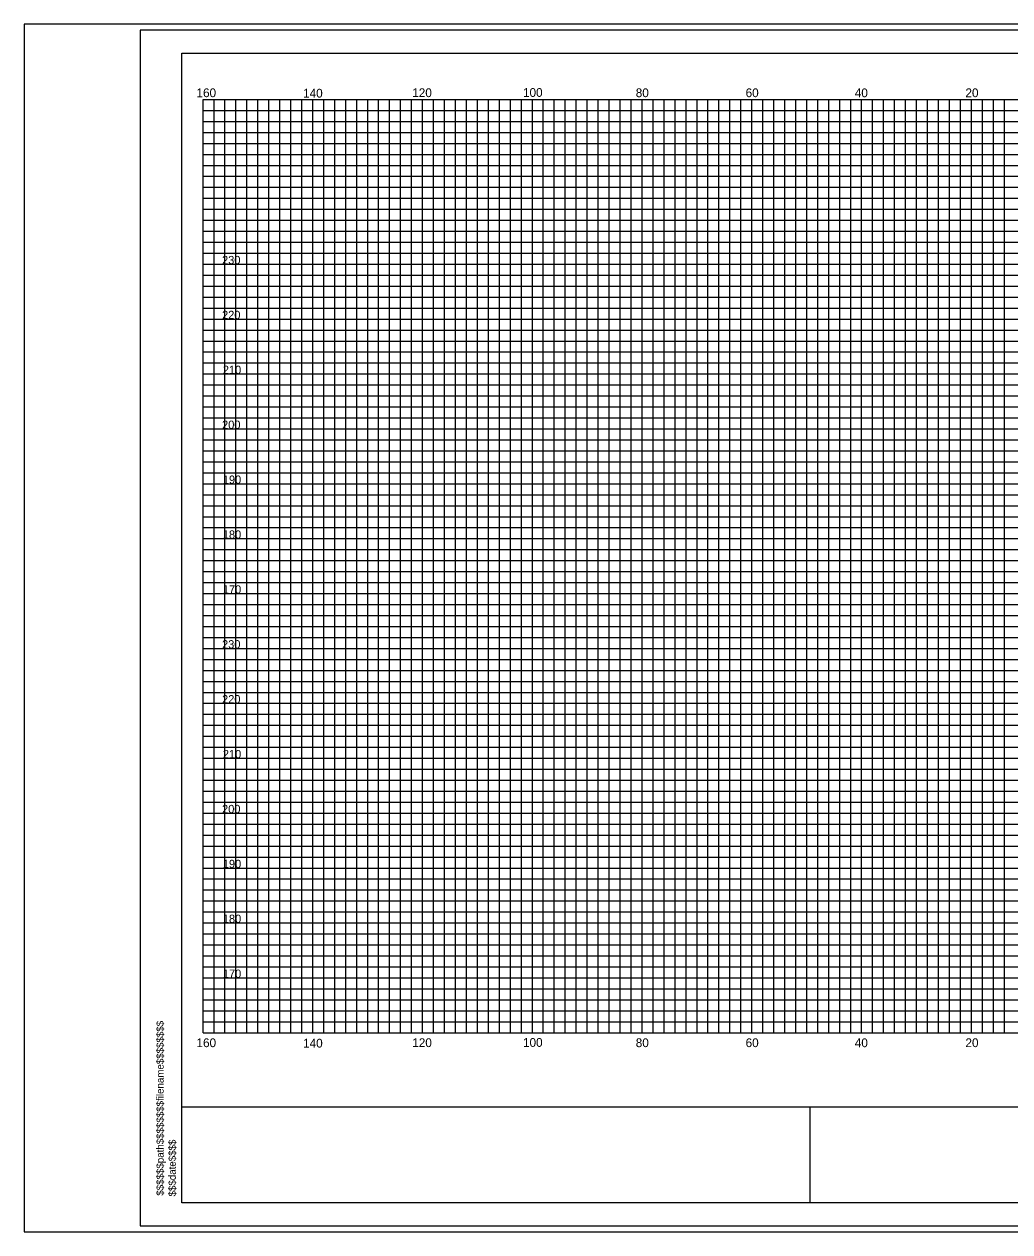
# Model space of a CAD drawing. Extents: x 967 to 1326, y 964 to 3144.
# Drawn here: x 967.4 to 1147, y 963.7 to 1183.7 of the extents above; entities that cross this region are included whole.
import ezdxf

# ---------------------------------------------------------------- set-up
doc = ezdxf.new("R2010")
doc.units = 0
for name, color, linetype in [('Default', 7, 'Continuous'), ('RD_GPK_XS_Cell', 7, 'Continuous'), ('RD_XS_ExGround', 7, 'Continuous'), ('RD_XS_ExPaveRet', 7, 'Continuous'), ('RD_XS_Misc_Line', 7, 'Continuous'), ('RD_XS_TX_Elev_EX', 7, 'Continuous'), ('RD_XS_TX_Station', 7, 'Continuous')]:
    doc.layers.add(name, color=color, linetype=linetype)

msp = doc.modelspace()

# ---------------------------------------------------------------- linework, layer by layer
at = {"layer": 'RD_GPK_XS_Cell'}
for p, q in [((1000, 1170), (1320, 1170)), ((1000, 1000), (1000, 1170)), ((1010, 1000), (1010, 1170)), ((1020, 1000), (1020, 1170)), ((1030, 1000), (1030, 1170)), ((1040, 1000), (1040, 1170)), ((1050, 1000), (1050, 1170)), ((1060, 1000), (1060, 1170)), ((1070, 1000), (1070, 1170)), ((1080, 1000), (1080, 1170)), ((1090, 1000), (1090, 1170)), ((1100, 1000), (1100, 1170)), ((1110, 1000), (1110, 1170)), ((1120, 1000), (1120, 1170)), ((1130, 1000), (1130, 1170)), ((1140, 1000), (1140, 1170)), ((1000, 1160), (1320, 1160)), ((1000, 1150), (1320, 1150)), ((1000, 1140), (1320, 1140)), ((1000, 1130), (1320, 1130)), ((1000, 1120), (1320, 1120)), ((1000, 1110), (1320, 1110)), ((1000, 1100), (1320, 1100)), ((1000, 1090), (1320, 1090)), ((1000, 1080), (1320, 1080)), ((1000, 1070), (1320, 1070)), ((1000, 1060), (1320, 1060)), ((1000, 1050), (1320, 1050)), ((1000, 1040), (1320, 1040)), ((1000, 1030), (1320, 1030)), ((1000, 1020), (1320, 1020)), ((1000, 1010), (1320, 1010)), ((1000, 1000), (1320, 1000))]:
    msp.add_line(p, q, dxfattribs=at)
at = {"layer": 'RD_XS_ExGround'}
for p, q in [((1002, 1000), (1002, 1170)), ((1004, 1000), (1004, 1170)), ((1006, 1000), (1006, 1170)), ((1008, 1000), (1008, 1170)), ((1012, 1000), (1012, 1170)), ((1014, 1000), (1014, 1170)), ((1016, 1000), (1016, 1170)), ((1018, 1000), (1018, 1170)), ((1022, 1000), (1022, 1170)), ((1024, 1000), (1024, 1170)), ((1026, 1000), (1026, 1170)), ((1028, 1000), (1028, 1170)), ((1032, 1000), (1032, 1170)), ((1034, 1000), (1034, 1170)), ((1036, 1000), (1036, 1170)), ((1038, 1000), (1038, 1170)), ((1042, 1000), (1042, 1170)), ((1044, 1000), (1044, 1170)), ((1046, 1000), (1046, 1170)), ((1048, 1000), (1048, 1170)), ((1052, 1000), (1052, 1170)), ((1054, 1000), (1054, 1170)), ((1056, 1000), (1056, 1170)), ((1058, 1000), (1058, 1170)), ((1062, 1000), (1062, 1170)), ((1064, 1000), (1064, 1170)), ((1066, 1000), (1066, 1170)), ((1068, 1000), (1068, 1170)), ((1072, 1000), (1072, 1170)), ((1074, 1000), (1074, 1170)), ((1076, 1000), (1076, 1170)), ((1078, 1000), (1078, 1170)), ((1082, 1000), (1082, 1170)), ((1084, 1000), (1084, 1170)), ((1086, 1000), (1086, 1170)), ((1088, 1000), (1088, 1170)), ((1092, 1000), (1092, 1170)), ((1094, 1000), (1094, 1170)), ((1096, 1000), (1096, 1170)), ((1098, 1000), (1098, 1170)), ((1102, 1000), (1102, 1170)), ((1104, 1000), (1104, 1170)), ((1106, 1000), (1106, 1170)), ((1108, 1000), (1108, 1170)), ((1112, 1000), (1112, 1170)), ((1114, 1000), (1114, 1170)), ((1116, 1000), (1116, 1170)), ((1118, 1000), (1118, 1170)), ((1122, 1000), (1122, 1170)), ((1124, 1000), (1124, 1170)), ((1126, 1000), (1126, 1170)), ((1128, 1000), (1128, 1170)), ((1132, 1000), (1132, 1170)), ((1134, 1000), (1134, 1170)), ((1136, 1000), (1136, 1170)), ((1138, 1000), (1138, 1170)), ((1142, 1000), (1142, 1170)), ((1144, 1000), (1144, 1170)), ((1146, 1000), (1146, 1170)), ((1000, 1168), (1320, 1168)), ((1000, 1166), (1320, 1166)), ((1000, 1164), (1320, 1164)), ((1000, 1162), (1320, 1162)), ((1000, 1158), (1320, 1158)), ((1000, 1156), (1320, 1156)), ((1000, 1154), (1320, 1154)), ((1000, 1152), (1320, 1152)), ((1000, 1148), (1320, 1148)), ((1000, 1146), (1320, 1146)), ((1000, 1144), (1320, 1144)), ((1000, 1142), (1320, 1142)), ((1000, 1138), (1320, 1138)), ((1000, 1136), (1320, 1136)), ((1000, 1134), (1320, 1134)), ((1000, 1132), (1320, 1132)), ((1000, 1128), (1320, 1128)), ((1000, 1126), (1320, 1126)), ((1000, 1124), (1320, 1124)), ((1000, 1122), (1320, 1122)), ((1000, 1118), (1320, 1118)), ((1000, 1116), (1320, 1116)), ((1000, 1114), (1320, 1114)), ((1000, 1112), (1320, 1112)), ((1000, 1108), (1320, 1108)), ((1000, 1106), (1320, 1106)), ((1000, 1104), (1320, 1104)), ((1000, 1102), (1320, 1102)), ((1000, 1098), (1320, 1098)), ((1000, 1096), (1320, 1096)), ((1000, 1094), (1320, 1094)), ((1000, 1092), (1320, 1092)), ((1000, 1088), (1320, 1088)), ((1000, 1086), (1320, 1086)), ((1000, 1084), (1320, 1084)), ((1000, 1082), (1320, 1082)), ((1000, 1078), (1320, 1078)), ((1000, 1076), (1320, 1076)), ((1000, 1074), (1320, 1074)), ((1000, 1072), (1320, 1072)), ((1000, 1068), (1320, 1068)), ((1000, 1066), (1320, 1066)), ((1000, 1064), (1320, 1064)), ((1000, 1062), (1320, 1062)), ((1000, 1058), (1320, 1058)), ((1000, 1056), (1320, 1056)), ((1000, 1054), (1320, 1054)), ((1000, 1052), (1320, 1052)), ((1000, 1048), (1320, 1048)), ((1000, 1046), (1320, 1046)), ((1000, 1044), (1320, 1044)), ((1000, 1042), (1320, 1042)), ((1000, 1038), (1320, 1038)), ((1000, 1036), (1320, 1036)), ((1000, 1034), (1320, 1034)), ((1000, 1032), (1320, 1032)), ((1000, 1028), (1320, 1028)), ((1000, 1026), (1320, 1026)), ((1000, 1024), (1320, 1024)), ((1000, 1022), (1320, 1022)), ((1000, 1018), (1320, 1018)), ((1000, 1016), (1320, 1016)), ((1000, 1014), (1320, 1014)), ((1000, 1012), (1320, 1012)), ((1000, 1008), (1320, 1008)), ((1000, 1006), (1320, 1006)), ((1000, 1004), (1320, 1004)), ((1000, 1002), (1320, 1002))]:
    msp.add_line(p, q, dxfattribs=at)
at = {"layer": 'RD_XS_ExPaveRet'}
for points in [[(967.41, 963.72), (1326.28, 963.72), (1326.28, 1183.72), (967.41, 1183.72)], [(988.52, 964.84), (1326.28, 964.84), (1326.28, 1182.6), (988.52, 1182.6)]]:
    msp.add_lwpolyline(points, close=True, dxfattribs=at)
at = {"layer": 'RD_XS_TX_Elev_EX'}
for p, q in [((996.11, 968.98), (996.11, 1178.46)), ((996.11, 1178.46), (1323.89, 1178.46)), ((996.11, 986.49), (1323.89, 986.49)), ((1110.59, 968.98), (1110.59, 986.56)), ((1323.89, 968.98), (996.11, 968.98))]:
    msp.add_line(p, q, dxfattribs=at)
at = {"layer": 'RD_XS_TX_Station'}
msp.add_lwpolyline([(967.41, 963.72), (1326.28, 963.72), (1326.28, 1183.72), (967.41, 1183.72)], close=True, dxfattribs=at)

# ---------------------------------------------------------------- texts
at = {"layer": 'Default'}
for s, p in [('230', (1003.47, 1140)), ('220', (1003.47, 1130)), ('210', (1003.61, 1120)), ('200', (1003.47, 1110)), ('190', (1003.61, 1100)), ('180', (1003.61, 1090)), ('170', (1003.61, 1080)), ('230', (1003.47, 1070)), ('220', (1003.47, 1060)), ('210', (1003.61, 1050)), ('200', (1003.47, 1040)), ('190', (1003.61, 1030)), ('180', (1003.61, 1020)), ('170', (1003.61, 1010))]:
    msp.add_text(s, height=1.5, dxfattribs=at).set_placement(p)
for s, p in [('$$$$$$path$$$$$$$$filename$$$$$$$$', (992.83, 970.31)), ('$$$date$$$$', (995.04, 970.17))]:
    msp.add_text(s, height=1.3258, rotation=90, dxfattribs=at).set_placement(p)
at = {"layer": 'RD_XS_Misc_Line'}
for s, p in [('160', (998.81, 1170.42)), ('140', (1018.23, 1170.34)), ('120', (1038.12, 1170.43)), ('100', (1058.3, 1170.47)), ('80', (1078.84, 1170.42)), ('60', (1098.86, 1170.42)), ('40', (1118.75, 1170.41)), ('20', (1138.91, 1170.42)), ('160', (998.81, 997.37)), ('140', (1018.23, 997.29)), ('120', (1038.12, 997.38)), ('100', (1058.3, 997.42)), ('80', (1078.84, 997.37)), ('60', (1098.86, 997.37)), ('40', (1118.75, 997.36)), ('20', (1138.91, 997.37))]:
    msp.add_text(s, height=1.6, dxfattribs=at).set_placement(p)

doc.saveas('drawing.dxf')
